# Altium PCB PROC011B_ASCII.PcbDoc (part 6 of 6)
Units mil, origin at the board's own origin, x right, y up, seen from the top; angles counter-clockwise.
Board outline 3304 x 2569 mil, 6 copper layers (TOP, L2-GND1, L3-GND/SIG, L4-GND/SIG, L5-GND2, BOTTOM), stack 55.77 mil thick; 376 components, 289 nets, 1284 pads, 1755 vias.
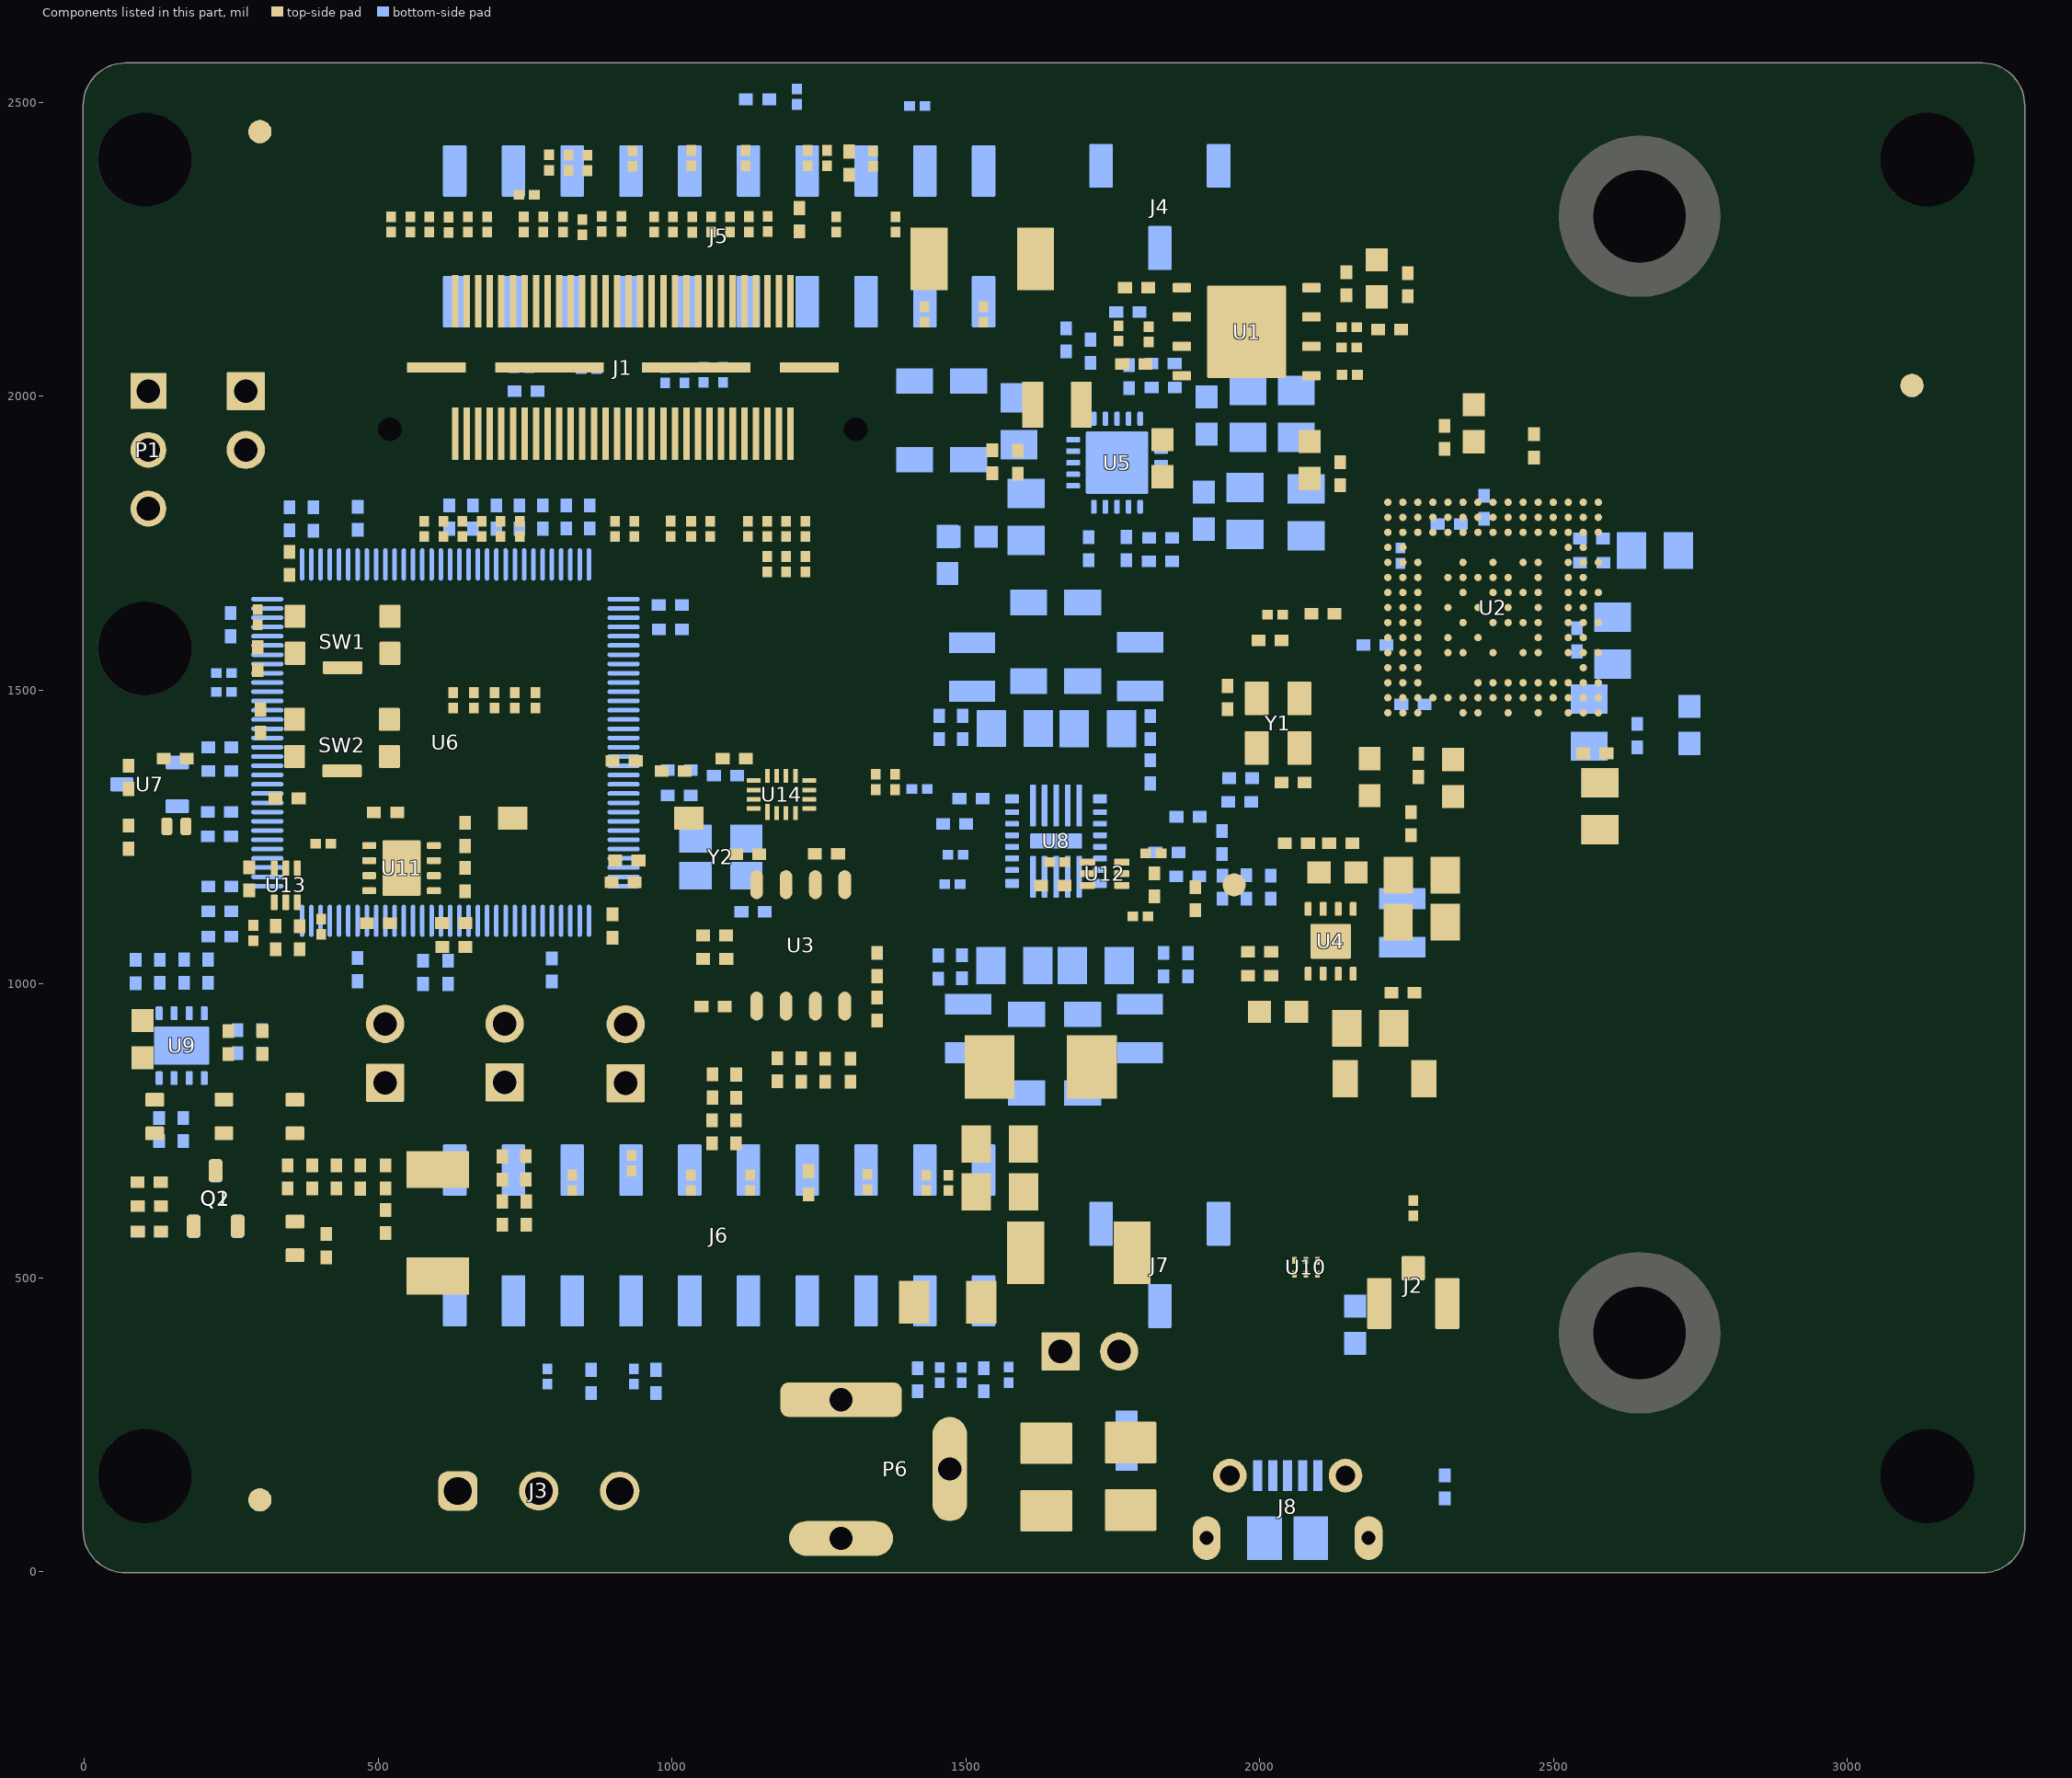
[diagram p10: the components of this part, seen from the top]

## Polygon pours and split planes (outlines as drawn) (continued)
5V_IN on TOP "TOP-5V_IN 2" (solid, pour order 995): 98 vertices, not listed, extent 511.75,336 769.75,518.6
5V_IN on TOP "TOP-5V_IN 3" (solid, remove dead copper, pour order 996): 169 vertices, not listed, extent 1558.65,336.3 1705.75,763.3
NetC1_2 on TOP "TOP-UNNAMED_41_CAPNONPOLARIZED_I63_" (solid, pour order 998): 2112.88,2196.48 2060.78,2196.48 2060.78,2172.88 2112.88,2172.88 2112.88,2196.48
5V_UNREG on TOP "TOP-5V_UNREG" (solid, pour order 1000): 122 vertices, not listed, extent 1729.45,342.3 1860.45,608.8
GND on TOP "TOP-GND" (solid, pour order 1006): 1894.98,2046.48 1842.88,2046.48 1842.88,2022.88 1894.98,2022.88 1894.98,2046.48
GND on TOP "TOP-GND 6" (solid, pour order 1014): 234 vertices, not listed, extent 1721.35,1161.1 1753.05,1226.6
GND on TOP "TOP-GND 7" (solid, pour order 1015): 162 vertices, not listed, extent 306.05,1160.99 369.63,1183.3
GND on TOP "TOP-GND 8" (solid, pour order 1016): 114 vertices, not listed, extent 1639.05,670 1773.15,928.2
GND on TOP "TOP-GND 9" (solid, pour order 1030): 217 vertices, not listed, extent 2250.67,1162.5 2332.75,1262.5
GND on TOP "TOP-GND 10" (solid, pour order 1031): 247 vertices, not listed, extent 187.75,1417.5 477.4,1552.5
GND on TOP "TOP-GND 11" (solid, pour order 1032): 146 vertices, not listed, extent 507.65,1089 572.15,1306
GND on TOP "TOP-GND 12" (solid, pour order 1036): 170 vertices, not listed, extent 1193.75,39 1828.75,265
GND on TOP "TOP-GND 14" (solid, pour order 1038): 72 vertices, not listed, extent 2573.71,1808.32 2613.84,1842.2
+3.3VD on TOP "TOP-+3.3VD" (solid, pour order 1041): 173 vertices, not listed, extent 2302.45,1845.65 2382.74,1941.4
GND on TOP "TOP-GND 3" (solid, remove dead copper, pour order 974): 2501.25,2155.5 2800.25,2155.5 2800.25,2457.5 2501.25,2457.5 2501.25,2155.5
GND on TOP "TOP-GND 13" (solid, remove dead copper, pour order 1044): 2847 vertices, not listed, extent 2201.45,15.1 3284.75,2549.4
GND on L4-GND/SIG "Top Layer-No Net" (solid, pour order 116): 43 vertices, not listed, extent 1376.03,1265.26 1898.12,2227.86
5V_UNREG on L4-GND/SIG "POWER2-No Net" (solid, remove dead copper, pour order 1046): 44 vertices, not listed, extent 1441.77,315 1865.48,1542.5
NetC85_2 on L4-GND/SIG "L4-UNNAMED_7_CAPNONPOLARIZED_I5_2" (solid, pour order 955): 96 vertices, not listed, extent 371.65,1146.2 422.25,1236.1
PMIC_1V2 on L4-GND/SIG "L4-PMIC_1V2" (solid, pour order 984): 1509 vertices, not listed, extent 1750.75,1574 2517.75,2258.4
AR_1V8 on L4-GND/SIG "L4-AR_1V8" (solid, pour order 986): 679 vertices, not listed, extent 2127.75,1077.15 2619.75,1752
5V_IN on L4-GND/SIG "L4-5V_IN" (solid, remove dead copper, pour order 997): 1026 vertices, not listed, extent 437.25,327 1727.75,2363.5
GND on L4-GND/SIG "L4-GND" (solid, pour order 1019): 555 vertices, not listed, extent 486.77,2124.33 1041.63,2468.58
GND on L4-GND/SIG "L4-GND 1" (solid, pour order 1020): 840 vertices, not listed, extent 2279.76,1480.82 2511.89,1757.58
GND on L4-GND/SIG "L4-GND 3" (solid, remove dead copper, pour order 1022): 2496 vertices, not listed, extent 16,16 3284,2549
GND on L4-GND/SIG "L4-GND 4" (solid, pour order 1023): 1170 vertices, not listed, extent 1011,2201.12 1728.04,2476.59
PMIC_2V3 on BOTTOM "BOTTOM-PMIC_2V3" (solid, pour order 958): 127 vertices, not listed, extent 1662.75,791 1947.35,900.66
PMIC_2V3 on BOTTOM "BOTTOM-PMIC_2V3 1" (solid, pour order 960): 146 vertices, not listed, extent 2140.55,968.7 2284.45,1079.3
MCU_5V on BOTTOM "BOTTOM-MCU_5V" (solid, pour order 961): 149 vertices, not listed, extent 517.75,626.5 686.75,759.5
MCU_5V on BOTTOM "BOTTOM-MCU_5V 1" (solid, pour order 964): 98 vertices, not listed, extent 1868.75,510 1993.75,651
PMIC_1V8 on BOTTOM "BOTTOM-PMIC_1V8" (solid, remove dead copper, pour order 973): 1183 vertices, not listed, extent 1339.97,801.5 1702.75,1952.5
AR_VOUT_PA on BOTTOM "BOTTOM-AR_VOUT_PA" (solid, pour order 976): 138 vertices, not listed, extent 2539.75,1315 2755.75,1427
PMIC_1V2 on BOTTOM "BOTTOM-PMIC_1V2" (solid, pour order 983): 299 vertices, not listed, extent 1663,1563 1950.75,1709.25
AR_1V8 on BOTTOM "BOTTOM-AR_1V8" (solid, pour order 987): 91 vertices, not listed, extent 2526.75,1593 2629.75,1638.98
AR_1V8 on BOTTOM "BOTTOM-AR_1V8 1" (solid, pour order 988): 124 vertices, not listed, extent 2147.75,1120 2286.65,1256.3
AR_1P3_RF2 on BOTTOM "BOTTOM-AR_1P3_RF2" (solid, pour order 990): 1059 vertices, not listed, extent 1818.8,1431.4 2987.75,2118
AR_1P3_RF1 on BOTTOM "BOTTOM-AR_1P3_RF1" (solid, pour order 992): 937 vertices, not listed, extent 1821.75,1607 2812.73,1963.7
PMICOUT_3V3 on BOTTOM "BOTTOM-PMICOUT_3V3" (solid, pour order 999): 176 vertices, not listed, extent 1453.77,1563.04 1642.75,1711.5
5V_UNREG on BOTTOM "BOTTOM-5V_UNREG" (solid, remove dead copper, pour order 1002): 183 vertices, not listed, extent 1514.45,1002.3 1620.75,1218.3
5V_UNREG on BOTTOM "BOTTOM-5V_UNREG 1" (solid, pour order 1003): 202 vertices, not listed, extent 1686.8,1002.3 1813.8,1218.5
5V_UNREG on BOTTOM "BOTTOM-5V_UNREG 2" (solid, pour order 1004): 209 vertices, not listed, extent 1687.75,1267.5 1787.85,1475.66
5V_UNREG on BOTTOM "BOTTOM-5V_UNREG 3" (solid, pour order 1005): 200 vertices, not listed, extent 1525.15,1267.5 1619.3,1475.26
GND on BOTTOM "BOTTOM-GND" (solid, pour order 1008): 21 vertices, not listed, extent 2421.7,31.02 3277.75,827.5
GND on BOTTOM "BOTTOM-GND 1" (solid, pour order 1013): 2497.25,2153.5 2796.25,2153.5 2796.25,2455.5 2497.25,2455.5 2497.25,2153.5
GND on BOTTOM "BOTTOM-GND 2" (solid, pour order 1033): 124 vertices, not listed, extent 1364.75,1971.5 1621.05,2069.85
GND on BOTTOM "BOTTOM-GND 3" (solid, pour order 1034): 510 vertices, not listed, extent 1703,307 2093.73,726.5
GND on BOTTOM "BOTTOM-GND 5" (solid, pour order 1037): 98 vertices, not listed, extent 1882.75,1982.35 2102.75,2147.5
GND on BOTTOM "BOTTOM-GND 6" (solid, pour order 1039): 239 vertices, not listed, extent 1567.7,919.3 1734.3,1218.3
GND on BOTTOM "BOTTOM-GND 7" (solid, pour order 1040): 307 vertices, not listed, extent 1568.8,1267.5 1736.9,1546
GND on BOTTOM "BOTTOM-GND 4" (solid, remove dead copper, pour order 1035): 2173 vertices, not listed, extent 1878.77,15.7 3284.85,2549.9
MCU_5V on L3-GND/SIG "L3-MCU_5V" (solid, pour order 963): 517 vertices, not listed, extent 507.75,406 1962.23,755.48
GND on L3-GND/SIG "L3-GND" (solid, pour order 1011): 2507.75,2437.5 2777.75,2437.5 2777.75,2182.5 2597.75,2182.5 2507.75,2272.5 2507.75,2437.5
GND on L3-GND/SIG "L3-GND 1" (solid, pour order 1012): 2487.75,562.5 2787.75,562.5 2787.75,262.5 2487.75,262.5 2487.75,562.5
GND on L3-GND/SIG "L3-GND 2" (solid, pour order 1024): 146 vertices, not listed, extent 1858.06,1991.53 2249.71,2152.58
GND on L3-GND/SIG "L3-GND 3" (solid, pour order 1025): 344 vertices, not listed, extent 1505.88,1776.02 1989.21,2041.98
GND on L3-GND/SIG "L3-GND 4" (solid, pour order 1026): 147 vertices, not listed, extent 231.09,1463.5 468.73,1691.74
GND on L3-GND/SIG "L3-GND 5" (solid, pour order 1027): 744 vertices, not listed, extent 991.89,593.02 1910.98,1006.2
GND on L3-GND/SIG "L3-GND 6" (solid, pour order 1028): 2622 vertices, not listed, extent 1431.33,501.13 2744.73,1845.59
GND on L3-GND/SIG "L3-GND 7" (solid, remove dead copper, pour order 1029): 3094 vertices, not listed, extent 16,16 3284,2549
GND on L2-GND1 "L5-GND" (solid, remove dead copper, pour order 1018): 553 vertices, not listed, extent 16,16 3284,2549
GND on L2-GND1 "L2-GND" (solid, pour order 1009): 2524.75,2427 2524.75,2180 2769.75,2180 2769.75,2427 2524.75,2427
GND on L2-GND1 "L2-GND 1" (solid, pour order 1010): 2527.25,529.5 2527.25,282.5 2772.25,282.5 2772.25,529.5 2527.25,529.5
GND on L5-GND2 "L5-GND" (solid, remove dead copper, pour order 1017): 553 vertices, not listed, extent 16,16 3284,2549
no net on Mechanical 6 Ass bot (solid): 340.75,2450 ccw(c298.75,2450) 298.75,2492 ccw(c298.75,2450) 256.75,2450 ccw(c298.75,2450) 298.75,2408 ccw(c298.75,2450) 340.75,2450
no net on Mechanical 6 Ass bot (solid): 340.75,122 ccw(c298.75,122) 298.75,164 ccw(c298.75,122) 256.75,122 ccw(c298.75,122) 298.75,80 ccw(c298.75,122) 340.75,122
no net on Mechanical 6 Ass bot (solid): 3150.95,2033.2 ccw(c3108.95,2033.2) 3108.95,2075.2 ccw(c3108.95,2033.2) 3066.95,2033.2 ccw(c3108.95,2033.2) 3108.95,1991.2 ccw(c3108.95,2033.2) 3150.95,2033.2
no net on Mechanical 5 Ass top (solid): 340.75,122 ccw(c298.75,122) 298.75,164 ccw(c298.75,122) 256.75,122 ccw(c298.75,122) 298.75,80 ccw(c298.75,122) 340.75,122
no net on Mechanical 5 Ass top (solid): 3152.65,2018.46 ccw(c3110.65,2018.46) 3110.65,2060.46 ccw(c3110.65,2018.46) 3068.65,2018.46 ccw(c3110.65,2018.46) 3110.65,1976.46 ccw(c3110.65,2018.46) 3152.65,2018.46
no net on Mechanical 5 Ass top (solid): 340.75,2450 ccw(c298.75,2450) 298.75,2492 ccw(c298.75,2450) 256.75,2450 ccw(c298.75,2450) 298.75,2408 ccw(c298.75,2450) 340.75,2450

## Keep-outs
TOP:
  circle w10: c3136.31,162.5 r92.09
  circle w10: c3136.31,2402.5 r92.09
  circle w10: c102.75,162.5 r92.09
  circle w10: c102.75,1570.6 r92.09
  circle w10: c102.75,2402.5 r92.09
L2-GND1:
  circle w10: c520.13,1943.64 r44.95
  circle w10: c1312.65,1943.64 r44.95
  circle w10: c3136.31,2402.5 r100.82
  circle w10: c3136.31,162.5 r100.82
  circle w10: c3136.31,2402.5 r100.82
L3-GND/SIG:
  circle w10: c3136.31,2402.5 r100.82
  circle w10: c3136.31,162.5 r100.82
L4-GND/SIG:
  circle w10: c3136.31,2402.5 r100.82
  circle w10: c3136.31,162.5 r100.82
  circle w10: c1312.65,1943.64 r44.95
L5-GND2:
  circle w10: c3136.31,162.5 r100.82
  circle w10: c3136.31,2402.5 r100.82
  circle w10: c520.13,1943.64 r44.95
  circle w10: c1312.65,1943.64 r44.95
BOTTOM:
  circle w1: c3110.08,2018.14 r44
  circle w10: c3136.31,2402.5 r92.09
  circle w10: c3136.31,162.5 r92.09
Keep-Out Layer:
  text "KEEP OUT LAYER" at -1318.01,-1032.33 h75

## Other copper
TOP:
  text "TOP" at -1316.15,-1038.69 h75
L2-GND1:
  text "LAYER-2 GND1" at -1293.22,-1034.39 h75
L3-GND/SIG:
  text "LAYER-3 GND/SIGNAL" at -1349.73,-1034.31 h75
L4-GND/SIG:
  text "LAYER-4 GND/SIGNAL" at -1322.23,-1041.27 h75
L5-GND2:
  text "LAYER-5 GND2" at -1308.33,-1043.01 h75
BOTTOM:
  text "BOTTOM" at -1318.46,-1042.03 h75

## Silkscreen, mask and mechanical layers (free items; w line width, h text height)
Top Overlay:
  lines w10: 176.28,1919.69 179.6,1919.69 193.53,1905.76 193.53,1794.32 187.71,1800.14 200.17,1800.14 194.35,1794.32
  lines w30: 1378.75,904.5 1378.75,818 1459.85,818 ; 1378.75,1094.5 1378.75,1274.5 ; 1382.75,1830 1382.75,2242 ; 1700.75,2258 2146.75,2258 ; 1786.25,818 2088.75,818 ; 2268.75,2258 2474.75,2258 ; 2770.75,1968 2770.75,2182
  text "HD_CONN" at 467.92,2015.1 h30 r90
  text "VPP_1P7" at 381.32,1862.65 h30 r90
  text "1642-EVM" at 813.79,1694.33 h30
  text "GND" at 209.45,1680.5 h30 r90
  text "PROC011" at 775,1637.52 h30
  text "REV B" at 969.45,1635.95 h30
  text "GPIO1" at 620.25,1543 h30 r90
  text "ON" at 1079.14,1311 h30 r90
  text "NRST" at 615.01,1295.07 h30 r90
  text "SPI" at 709,1164 h30 r90
  text "CAN" at 1079.14,1153 h30 r90
  text "SOP0" at 1025.49,883.72 h30 r90
  text "5V" at 385.25,854.5 h30 r90
  text "NERR_OUT" at 211.42,848.5 h30 r90
  text "SOP1" at 821.68,840.86 h30 r90
  text "SOP2" at 615.55,835.13 h30 r90
  text "NRST" at 404.16,399.06 h30 r90
  text "5V_IN" at 1194.75,354 h30 r90
  text "GND" at 790.25,294 h30 r90
  text "CAN_L" at 1066.42,227.5 h30 r90
  text "CAN_H" at 542.42,226.5 h30 r90
  text "USB" at 2011.93,198.27 h30
  text "SILKSCREEN TOP" at -1339.97,-1029.03 h60
Bottom Overlay:
  drawing of 8192 lines, arcs and shapes, not listed
  text "GND" at 1745.25,2556 h30 r90
  text "GND" at 1845.25,2556 h30 r90
  text "3V3" at 1943.47,2549.66 h30 r90
  text "GND" at 596.45,2529.6 h30 r90
  text "20" at 1634.19,2423.68 h30 r90
  text "2" at 552.36,2404.47 h30 r90
  text "19" at 1638.64,2210.67 h30 r90
  text "1" at 544.91,2180.78 h30 r90
  text "P1" at 132.79,2073.5 h30
  text "P7" at 396.41,2020 h30
  text "P4" at 955.85,1005.8 h30
  text "P3" at 537.9,1001.27 h30
  text "P2" at 736.23,1000.15 h30
  text "GND" at 790.25,886 h30 r90
  text "GND" at 1845.25,776 h30 r90
  text "GND" at 1735.25,771 h30 r90
  text "20" at 1641.82,729.19 h30 r90
  text "2" at 553.44,705.94 h30 r90
  text "19" at 1656.65,524.84 h30 r90
  text "1" at 545.99,482.25 h30 r90
  text "P6" at 1317.41,338.79 h30
  text "P5" at 1877.7,327.72 h30
  text "J3" at 538.18,135.69 h30
  text "SILKSCREEN BOTTOM" at -1330.97,-1032.41 h75
Top Paste:
  text "SOLDERPASTE TOP" at -1322.76,-1029.77 h75
Bottom Paste:
  text "SOLDERPASTE BOTTOM" at -1315.43,-1031.21 h75
Top Solder:
  text "SOLDERMASK TOP" at -1325.23,-1033.37 h75
Bottom Solder:
  text "SOLDERMASK BOTTOM" at -1292.25,-1013.98 h75
OUTLINE:
  lines w4: 0,70 ccw(c70,70) 70,0 3230,0 ccw(c3230,70) 3300,70 3300,2495 ccw(c3230,2495) 3230,2565 70,2565 ccw(c70,2495) 0,2495 0,70
Board Dimensions:
  text "AT 4 PLACES" at -810,-280 h75
Mechanical 5 Ass top:
  lines w6: 163,2270 163,2286 174,2297 355,2297 405,2247 741,2247 747,2253 747,2256 ; 355.14,2202 420,2202 435,2217 897.05,2217 912,2231.95 912,2254 ; 974,2330 974,2349.96 985.04,2361 1276.02,2361 1291.02,2346 1361,2346 1376,2361 1376,2381 1391,2396 ; 1162.65,2337 1162.65,2337.65 1171,2346 1256.78,2346 1269.78,2333 1574,2333 1604,2363 1604,2371 ; 2111,2139 2111,2127.39 2113.39,2125
  lines w10: -2151.07,-1099.34 4448.93,-1099.34 ; -2151.07,-896 4450.93,-896 ; -2151.07,-692.67 -2151.07,-1302.67 1853.93,-1302.67 4450.93,-1302.67 4450.93,-692.67 -2150.57,-692.67 -2150.57,-1302.67 -575.07,-1302.67 ; 313.93,-1302.67 313.93,-692.67 ; 1580.93,-896 1580.93,-692.67 ; 2420.93,-896 2420.93,-692.67 ; 3042.93,-1309.17 3042.93,-1106.34
  text "COMPONENTS MARKED 'DNP' SHOULD NOT BE POPULATED." at -1592.26,2897.89 h60
  text "ASSEMBLY VARIANT:" at -1592.76,2782.39 h60
  text ".VariantName" at -556.76,2782.39 h60
  text "PCB VIEWED FROM TOP SIDE" at -2087.57,-824.84 h60
  text "BOARD #:" at 388.93,-824.84 h60
  text ".PRJ_Number" at 934.43,-824.84 h60
  text "REV:" at 1778.93,-824.84 h60
  text ".PCB_Rev" at 2070.43,-824.84 h60
  text "SVN REV:" at 2616.93,-824.84 h60
  text ".VersionControl_RevNumber" at 3122.93,-824.84 h60
  text "Assembly TOP" at -1818.81,-1016.17 h60
  text "TID #:" at 388.93,-1028.17 h60
  text ".TID" at 934.43,-1028.17 h60
  text "PLOT NAME =" at -2087.57,-1233.51 h60
  text ".plot_File_Name" at -1282.07,-1233.51 h35
  text "GENERATED    :" at 390.93,-1233.51 h60
  text ".Print_Date" at 1260.43,-1233.51 h60
  text ".Print_Time" at 1989.43,-1233.51 h60
  text "TEXAS INSTRUMENTS" at 3253.93,-1233.51 h60
Mechanical 6 Ass bot:
  lines w10: -2151.07,-896 4450.93,-896 ; -2149.07,-1099.34 4450.93,-1099.34 ; -743.07,-1309.17 -743.07,-1106.34 ; -121.07,-896 -121.07,-692.67 ; 718.93,-896 718.93,-692.67 ; 1985.93,-1302.67 1985.93,-692.67 ; 2874.93,-1302.67 4450.43,-1302.67 4450.43,-692.67 -2151.07,-692.67 -2151.07,-1302.67 445.93,-1302.67 4450.93,-1302.67 4450.93,-692.67
  text "COMPONENTS MARKED 'DNP' SHOULD NOT BE POPULATED." at 4243.43,-486.67 h60
  text ".VariantName" at 3199.43,-602.67 h60
  text "ASSEMBLY VARIANT:" at 4238.43,-602.67 h60
  text ".VersionControl_RevNumber" at -823.07,-824.84 h60
  text "SVN REV:" at -317.07,-824.84 h60
  text ".PCB_Rev" at 229.43,-824.84 h60
  text "REV:" at 520.93,-824.84 h60
  text ".PRJ_Number" at 1365.43,-824.84 h60
  text "BOARD #:" at 1910.93,-824.84 h60
  text "PCB VIEWED FROM BOTTOM SIDE" at 4387.43,-824.84 h60
  text ".TID" at 1365.43,-1028.17 h60
  text "TID #:" at 1910.93,-1028.17 h60
  text "ASSEMBLY BOTTOM" at 4003,-1028 h60
  text "TEXAS INSTRUMENTS" at -954.07,-1233.51 h60
  text ".Print_Time" at 310.43,-1233.51 h60
  text ".Print_Date" at 1039.43,-1233.51 h60
  text "GENERATED    :" at 1908.93,-1233.51 h60
  text ".plot_File_Name" at 3581.93,-1233.51 h35
  text "PLOT NAME =" at 4387.43,-1233.51 h60
M9 Title Sheet:
  lines w10: -2351.2,871.62 -2151.2,871.62 ; -2351.2,3246.62 -2151.2,3246.62 ; -2351.2,5621.62 -2151.2,5621.62 ; 148.8,-1503.38 148.8,-1303.38 ; 148.8,7796.62 148.8,7996.62 ; 2648.8,-1503.38 2648.8,-1303.38 ; 2648.8,7796.62 2648.8,7996.62 ; 4461.3,-1303.38 4461.3,-693.38 9443.8,-693.38 ; 5148.8,-1503.38 5148.8,-1303.38 ; 5148.8,7796.62 5148.8,7996.62 ; 7648.8,-1503.38 7648.8,-1303.38 ; 7648.8,7796.62 7648.8,7996.62 ; 9443.8,-1303.38 9443.8,-693.38 ; 9443.8,-993.38 12443.8,-993.38 ; 9443.8,-393.38 12443.8,-393.38 ; 9444.8,200.62 12444.8,200.62 ; 10148.8,-1503.38 10148.8,-1303.38 ; 10148.8,7796.62 10148.8,7996.62 ; 10948.8,-1293.38 10948.8,-693.38 ; 12443.8,-693.38 9443.8,-693.38 ; 12443.8,-93.38 9443.8,-93.38 ; 12448.8,-103.38 12448.8,-1303.38 ; 12448.8,701.12 9444.8,701.12 9443.8,701.12 9443.8,200.62 9443.8,-93.38 ; 12448.8,871.62 12648.8,871.62 ; 12448.8,3246.62 12648.8,3246.62 ; 12448.8,5621.62 12648.8,5621.62 ; 9443.8,-693.38 9443.8,-93.38 ; 12448.8,-1303.38 -2151.2,-1303.38 -2151.2,7796.62 12448.8,7796.62 12448.8,-1303.38 ; -2351.2,-1503.38 12648.8,-1503.38 12648.8,7996.62 -2351.2,7996.62 -2351.2,-1503.38
  text "1" at -1119.86,7866.62 h70
  text "2" at 1375.8,7866.62 h70
  text "3" at 3865.14,7866.62 h70
  text "4" at 6371.81,7866.62 h70
  text "5" at 8870.8,7866.62 h70
  text "6" at 11375.8,7866.62 h70
  text "A" at -2276.2,6723.62 h70
  text "A" at 12523.8,6723.62 h70
  text "B" at -2276.2,4343.62 h70
  text "B" at 12523.8,4343.62 h70
  text "C" at -2276.2,1968.62 h70
  text "C" at 12523.8,1968.62 h70
  text "PROJECT TITLE:" at 9483.8,107.62 h45
  text ".PRJ_Title" at 9533.8,-25.71 h50
  text "DESIGNED FOR:" at 9483.8,-193.38 h45
  text ".PRJ_Customer" at 9533.8,-333.38 h70
  text "D" at -2276.2,-401.38 h70
  text "D" at 12523.8,-401.38 h70
  text "FILE NAME:" at 9483.8,-493.38 h45
  text ".PCB_File_Name_No_Path" at 9533.8,-613.38 h70
  text "Texas Instruments (TI) and/or its licensors do not warrant the accuracy or completeness of this specification" at 4514.3,-775.22 h45
  text "ENGINEER:" at 9483.8,-783.38 h45
  text "LAYOUT BY:" at 10988.8,-783.38 h45
  text "or any information contained therein. TI and/or its licensors do not warrant that this design will meet" at 4469.31,-887.88 h45
  text ".PRJ_Engineer" at 9533.8,-938.37 h70
  text ".PCB_Layout" at 11039.3,-938.37 h70
  text "the specifications, will be suitable for your application or fit for any particular purpose, or will operate in" at 4469.31,-1000.55 h45
  text "ALTIUM DESIGNER VERSION:" at 10988.8,-1093.38 h45
  text "an implementation. TI and/or its licensors do not warrant that the design is production worthy. You should" at 4469.31,-1113.21 h45
  text "completely validate and test your design implementation to confirm the system functionality for your application." at 4514.3,-1225.88 h45
  text ".print_Scale" at 9533.8,-1226.71 h70
  text ".Application_BuildNumber" at 11039.3,-1226.71 h70
  text "1" at -1119.86,-1433.38 h70
  text "2" at 1375.8,-1433.38 h70
  text "3" at 3865.14,-1433.38 h70
  text "4" at 6371.81,-1433.38 h70
  text "5" at 8870.8,-1433.38 h70
  text "6" at 11375.8,-1433.38 h70
LOGO_HOT:
  drawing of 189 lines, arcs and shapes, not listed
  text "DESIGN INFORMATION" at 10521.82,6186.29 h60
  text "MIL" at 11183,6056 h60
  text "MIN. TRACK WIDTH:" at 9877.26,6054.17 h60
  text "4" at 10973.5,6054.17 h60
  text "4" at 10965.36,5957.06 h60
  text "MIL" at 11182.26,5931 h60
  text "MIN. CLEARANCE:" at 9877.26,5930.04 h60
  text "MIL" at 11185,5807 h60
  text "MIN. VIA PAD SIZE:" at 9877.26,5805.92 h60
  text "13.77" at 10873,5798 h60
  text "0.05mm (2MIL)" at 10572.26,5676.02 h60
  text "MINIMUM ANNULAR RING" at 9548.03,5667.79 h60
  text "EXTERNAL" at 11280.26,5667.79 h60
  text "PER" at 9748.03,5557.67 h60
  text "IPC-D-275 CLASS 2 LEVEL C" at 9968.03,5557.66 h60
  text "MIL, HOLES" at 11456.26,5457.19 h60
  text "+/-" at 11063.8,5448.6 h60
  text "+/-" at 11917.8,5448.6 h60
  text "REGISTRATION TOLERANCES:" at 9548.03,5447.54 h60
  text "METAL" at 10747.8,5447.54 h60
  text "2" at 11324,5447.54 h60
  text "3" at 12157,5447.54 h60
  text "MIL" at 12273.26,5447.54 h60
  text "HOLE SIZE TOLERANCE (UNLESS OTHERWISE SPECIFIED):" at 9548.03,5349.22 h60
  text "+/-" at 11917.8,5346.35 h60
  text "3" at 12157,5345.29 h60
  text "MIL" at 12273.26,5345.29 h60
  text "MATERIAL:" at 9473.26,5207.64 h60
  text "FR-4 High Tg" at 10459.7,5079.12 h60
  text "X" at 11197.39,5075.36 h60
  text "FR-408" at 9894.26,5066.61 h60
  text "OTHER" at 11382.26,5066.61 h60
  text "REFER STACKUP" at 11710.91,5051.35 h60
  text "THICKNESS:" at 9489.68,4927.16 h60
  text "X" at 10000.66,4924.28 h60
  text "56.21 MIL (1.43mm) +/-10%" at 10100.96,4922.18 h60
  text "OTHER" at 11499.26,4915.36 h60
  text "TOLERANCE:" at 9548.03,4777.04 h60
  text "X" at 10396.26,4777.04 h60
  text "ANSI IPC-6012 TYPE 3 CLASS 2" at 10574.28,4777.04 h60
  text "OTHER +/-" at 10574.26,4632.85 h60
  text "BOW & TWIST:" at 9548.03,4487.66 h60
  text "X" at 10396.26,4487.66 h60
  text "ANSI IPC-6012 TYPE 3 CLASS 2" at 10574.28,4487.66 h60
  text "OTHER +/-" at 10574.26,4340.97 h60
  text "DRILLING:" at 9473.26,4210.35 h60
  text "NC_DRILL FILES" at 11234.26,4105.16 h60
  text "REFERENCE:" at 9548.03,4101.22 h60
  text "X" at 10205.26,4101.13 h60
  text "AS SHOWN" at 10383.26,4101.22 h60
  text "X" at 11106.26,4101.22 h60
  text "OTHER" at 11532.26,3958.97 h60
  text "PTH COPPER THICKNESS:" at 9547.71,3955.44 h60
  text "X" at 10686.94,3955.44 h60
  text "20-30 um" at 10814.94,3955.44 h60
  text "BOARD FINISH:" at 9473.26,3807.85 h60
  text "SILKSCREEN:" at 9628.48,3697.72 h60
  text "X" at 10586.26,3697.72 h60
  text "TOP" at 10703.26,3697.72 h60
  text "X" at 11096.26,3697.72 h60
  text "BOTTOM" at 11214.26,3697.72 h60
  text "SILKSCREEN COLOR:" at 9628.48,3542.53 h60
  text "X" at 10585.26,3542.53 h60
  text "WHITE" at 10703.26,3542.53 h60
  text "OTHER" at 11214.26,3542.53 h60
  text "GREEN" at 10834.26,3399.08 h60
  text "OTHER" at 11452.26,3399.08 h60
  text "X" at 11296.74,3395.1 h60
  text "RED" at 11875.95,3395.11 h60
  text "SOLDER RESIST COLOR:" at 9628.48,3392.22 h60
  text "X" at 10716.26,3244.83 h60
  text "MATTE" at 10834.26,3244.83 h60
  text "SEMI-GLOSS" at 11451.8,3244.19 h60
  text "IMMERSION GOLD (ENIG)" at 10534.26,3072.06 h60
  text "ENEPIG" at 11871.8,3064.84 h60
  text "SURFACE FINISH:" at 9473.26,3063.84 h60
  text "IMM SILVER" at 11653,2932 h60
  text "IMM. TIN/SILVER OR EQUIV" at 9802.8,2926.52 h60
  text "X" at 11058.66,2926.28 h60
  text "OTHER" at 11234.26,2922.59 h60
  text "ARRAY/PANEL:" at 9473.26,2767.21 h60
  text "CUT AND TRIM PER M1 BOARD OUTLINE" at 10534.26,2758.99 h60
  text "X" at 10355.66,2746.28 h60
  text "N.C. ROUTE" at 10534.26,2623.02 h60
  text "V. SCORE" at 11400.26,2623.02 h60
  text "CERTIFICATION:" at 9473.26,2493.89 h60
  text "MATERIALS AND WORKMANSHIP FOR ALL PCBS" at 10198.26,2493.89 h60
  text "TO MEET OR EXCEED THE REQUIREMENTS OF:" at 10198.26,2399.83 h60
  text "X" at 9835.77,2271.2 h60
  text "ANSI IPC-A-600F CLASS ->" at 9963.76,2271.2 h60
  text "X" at 11611.77,2271.2 h60
  text "2" at 11721.76,2271.2 h60
  text "1" at 11406.76,2269.7 h60
  text "3" at 12075.76,2269.7 h60
  text "X" at 10647.77,2123.51 h60
  text "RoHS" at 10775.76,2123.51 h60
  text "OTHER" at 11420.16,2123.51 h60
  text "PER ORDER" at 11817.22,2123.51 h60
  text "ALL BOARDS MUST MEET OR EXCEED UL94-V0 REQUIREMENTS." at 9500.8,1969.69 h60
  text "PCB MUST BEAR THE UL94V-0 UL REGISTERED MATERIAL ID NUMBER" at 9500.8,1853.62 h60
  text "ADDITIONAL REQUIREMENTS:" at 9473.26,1684.2 h60
  text "MICROSECTION:" at 9548.03,1577.07 h60
  text "YES" at 10453.76,1577.07 h60
  text "REQUIRED" at 11315.26,1432.74 h60
  text "BARE BOARD ELEC. TEST:" at 9548.03,1429.88 h60
  text "NONE" at 10853.76,1429.88 h60
  text "X" at 11197.26,1429.88 h60
  text "PER ORDER" at 11907.26,1429.88 h60
  text "XX MIL VIAS REQUIRE NON-CONDUCTIVE FILL AND PLANARIZE" at 9662.75,1281.5 h59
  text "XX MIL VIAS REQUIRE CONDUCTIVE FILL AND PLANARIZE" at 9648.75,1125.5 h60
  text "OUTER XX MIL TRACES REQUIRE 50 OHM SINGLE-ENDED IMPEDANCE" at 9641.75,955.5 h58
  text "OUTER XX ML TRACES REQUIRE 100 OHM DIFFERENTIAL PAIR" at 9662.75,834.5 h60
  text "IMPEDANCE CONTROL TRACES" at 9741.75,726.5 h60
M11 Gerber Information:
  lines w10: -2151.29,-1100.49 4448.71,-1100.49 ; -2151.29,-897.15 4450.71,-897.15 ; -2151.29,-693.82 -2151.29,-1303.82 1853.71,-1303.82 4450.71,-1303.82 4450.71,-693.82 -2150.79,-693.82 -2150.79,-1303.82 -575.29,-1303.82 ; 313.71,-1303.82 313.71,-693.82 ; 1580.71,-897.15 1580.71,-693.82 ; 2420.71,-897.15 2420.71,-693.82 ; 3052.83,-1282.27 3052.83,-1079.44
  text "ALL ARTWORK VIEWED FROM TOP SIDE" at -2087.79,-825.99 h60
  text "BOARD #:" at 388.71,-825.99 h60
  text ".PRJ_Number" at 934.21,-825.99 h60
  text "REV:" at 1778.71,-825.99 h60
  text ".PCB_Rev" at 2070.21,-825.99 h60
  text "SVN REV:" at 2616.71,-825.99 h60
  text ".VersionControl_RevNumber" at 3122.71,-825.99 h60
  text "LAYER NAME =" at -2087.79,-1028.81 h60
  text "TID #:" at 388.71,-1029.32 h60
  text ".TID" at 934.21,-1029.32 h60
  text ".plot_File_Name" at -1429,-1231 h50
  text "PLOT NAME =" at -2087.79,-1234.65 h60
  text "GENERATED    :" at 390.71,-1234.65 h60
  text ".Print_Date" at 1260.21,-1234.65 h60
  text ".Print_Time" at 1989.21,-1234.65 h60
  text "TEXAS INSTRUMENTS" at 3253.71,-1234.65 h60
Mechanical 12:
  drawing of 399 lines, arcs and shapes, not listed
  text "Layer" at 3775.5,7076.5 h60
  text "Name" at 4185.41,7076.5 h60
  text "Material" at 5115.16,7076.5 h60
  text "Thickness" at 5974.92,7076.5 h60
  text "Constant" at 6624.76,7076.5 h60
  text "Board Layer Stack" at 7194.62,7076.5 h60
  text "1" at 3775.5,6956.5 h60
  text "Top Overlay" at 4185.41,6956.5 h60
  text "2" at 3775.5,6836.5 h60
  text "Top Solder" at 4185.41,6836.5 h60
  text "Solder Resist" at 5115.16,6836.5 h60
  text "0.80mil" at 5974.92,6836.5 h60
  text "0" at 6624.76,6836.5 h60
  text "3" at 3775.5,6716.5 h60
  text "TOP" at 4185.41,6716.5 h60
  text "Copper" at 5115.16,6716.5 h60
  text "1.60mil" at 5974.92,6716.5 h60
  text "4" at 3775.5,6596.5 h60
  text "Dielectric1" at 4185.41,6596.5 h60
  text "RO4835 LOPRO" at 5115.16,6596.5 h60
  text "4.00mil" at 5974.92,6596.5 h60
  text "3.66" at 6624.76,6596.5 h60
  text "5" at 3775.5,6476.5 h60
  text "L2-GND1" at 4185.41,6476.5 h60
  text "Copper" at 5115.16,6476.5 h60
  text "1.40mil" at 5974.92,6476.5 h60
  text "6" at 3775.5,6356.5 h60
  text "Dielectric2" at 4185.41,6356.5 h60
  text "370HR" at 5115.16,6356.5 h60
  text "5.67mil" at 5974.92,6356.5 h60
  text "3.9" at 6624.76,6356.5 h60
  text "7" at 3775.5,6236.5 h60
  text "L3-GND/SIG" at 4185.41,6236.5 h60
  text "Copper" at 5115.16,6236.5 h60
  text "1.20mil" at 5974.92,6236.5 h60
  text "8" at 3775.5,6116.5 h60
  text "Dielectric3" at 4185.41,6116.5 h60
  text "370HR" at 5115.16,6116.5 h60
  text "28.00mil" at 5974.92,6116.5 h60
  text "4.36" at 6624.76,6116.5 h60
  text "9" at 3775.5,5996.5 h60
  text "L4-GND/SIG" at 4185.41,5996.5 h60
  text "Copper" at 5115.16,5996.5 h60
  text "1.20mil" at 5974.92,5996.5 h60
  text "10" at 3775.5,5876.5 h60
  text "Dielectric4" at 4185.41,5876.5 h60
  text "370HR" at 5115.16,5876.5 h60
  text "5.90mil" at 5974.92,5876.5 h60
  text "3.9" at 6624.76,5876.5 h60
  text "11" at 3775.5,5756.5 h60
  text "L5-GND2" at 4185.41,5756.5 h60
  text "Copper" at 5115.16,5756.5 h60
  text "1.20mil" at 5974.92,5756.5 h60
  text "12" at 3775.5,5636.5 h60
  text "Dielectric5" at 4185.41,5636.5 h60
  text "370HR" at 5115.16,5636.5 h60
  text "4.00mil" at 5974.92,5636.5 h60
  text "4.26" at 6624.76,5636.5 h60
  text "13" at 3775.5,5516.5 h60
  text "BOTTOM" at 4185.41,5516.5 h60
  text "Copper" at 5115.16,5516.5 h60
  text "1.60mil" at 5974.92,5516.5 h60
  text "14" at 3775.5,5396.5 h60
  text "Bottom Solder" at 4185.41,5396.5 h60
  text "Solder Resist" at 5115.16,5396.5 h60
  text "0.80mil" at 5974.92,5396.5 h60
  text "0" at 6624.76,5396.5 h60
  text "15" at 3775.5,5276.5 h60
  text "Bottom Overlay" at 4185.41,5276.5 h60
Mechanical 14:
  text "NOTES: UNLESS OTHERWISE SPECIFIED." at 3982.31,2648.8 h60
  text "1. ALL VIAS ARE TENTED ON BOTH SIDES UNLESS SOLDERMASK OPENED IN GERBER." at 3986.8,2136.01 h60
  text "2. ALL VIAS ON PAD INCLUDING BGA AREA SHOULD BE FILLED WITH NON CONDUCTIVE EPOXY AND SURFACE SHOULD BE FLAT" at 3988.14,1986.34 h60
  text "BGA AREA VIAS SHOULD BE CAPPED WITH COPPER PLATING TO ENSURE FLAT SURFACE" at 4158.14,1879.34 h60
  text "REFER VIA FILL DOCUMENT TO IDENTIFY THE VIAS TO BE FILLED" at 4158.14,1775.34 h60
  text "FLATNESS TOLERANCE FOR VIA ON PADS: +0.000 /- 0.001 INCHES ON BOTH SIDES." at 4158.14,1666.34 h60
  text "3. MANUFACTURER'S IDENTIFICATION,DATECODE LETTER SHALL BE SILKSCREENED ON SOLDER SIDE" at 3974.61,1494.94 h60
  text "OF THE BOARD." at 4144.61,1381.94 h60
  text "4. TRACE WIDTH SHOULD BE ACCURATELY ETCHED. MAX TOLERANCE +/- 1 MIL" at 3974.61,1267.94 h60
  text "5. REFER STACKUP DOCUMENT FOR IMPEDANCE CONTROL TRACES ON LAYER 1." at 3960,1134.48 h60
  text "50 OHM SINGLE ENDED AND 100 OHM DIFFERENTIAL IMPEDANCE CONTROL TRACES." at 4071,1023 h60
  text "6. SOLDER MASK OPENING IS KEPT SAME SIZE AS PAD (1:1)." at 3980,876.35 h60
  text "THE MANUFACTURER IS REQUESTED TO RESIZE IT AS PER THEIR SOLDERMASK TOLERANCE EXCEPT NPTH DRILL AND FIDUCIALS." at 4090,722.46 h60
Mechanical 16:
  lines w0.16: -48930.49,-49088.31 cw(c-48930.49,-49085.55) -48933.25,-49085.55 -48933.25,-48990.08 cw(c-48930.49,-48990.08) -48930.49,-48987.32
  lines w0.79: -48810.48,-49133.52 -48810.48,-49166 -48672.68,-49166 -48672.68,-49133.52 ; -48769.14,-49166 -48769.14,-49133.52
FAB_DWG:
  circle w10: c54,5806.91 r27.55
  circle w10: c54,5435.03 r16.53
  circle w10: c54,5435.03 r27.55
  lines w10: 26.45,5531.44 81.55,5531.44 81.55,5586.54 26.45,5586.54 26.45,5531.44 ; 26.45,5669.18 40.23,5669.18 54,5655.4 67.77,5669.18 81.55,5669.18 67.77,5682.95 81.55,5696.72 67.77,5696.72 54,5710.49 40.23,5696.72 26.45,5696.72 40.23,5682.95 26.45,5669.18 ; 26.45,5958.41 81.55,5958.41 54,5903.32 26.45,5958.41 ; 26.45,6027.27 81.55,6027.27 81.55,6082.37 26.45,6082.37 26.45,6027.27 ; 26.45,6165 40.23,6165 40.23,6151.23 67.77,6151.23 67.77,6165 81.55,6165 81.55,6192.55 67.77,6192.55 67.77,6206.32 40.23,6206.32 40.23,6192.55 26.45,6192.55 26.45,6165 ; 26.45,6275.19 54,6288.96 81.55,6275.19 67.77,6302.74 81.55,6330.28 54,6316.51 26.45,6330.28 40.23,6302.74 26.45,6275.19 ; 26.45,6399.15 26.45,6412.92 40.23,6426.69 26.45,6440.47 26.45,6454.24 40.23,6454.24 54,6440.47 67.77,6454.24 81.55,6454.24 81.55,6440.47 67.77,6426.69 81.55,6412.92 81.55,6399.15 67.77,6399.15 54,6412.92 40.23,6399.15 26.45,6399.15 ; 26.45,6550.65 54,6523.1 81.55,6550.65 54,6578.2 26.45,6550.65 ; 26.45,6660.83 40.23,6660.83 54,6647.06 67.77,6660.83 81.55,6660.83 67.77,6674.61 81.55,6688.38 67.77,6688.38 54,6702.15 40.23,6688.38 26.45,6688.38 40.23,6674.61 26.45,6660.83 ; 26.45,6826.11 81.55,6826.11 54,6771.02 26.45,6826.11 ; 37.47,5542.46 70.53,5542.46 70.53,5575.52 37.47,5575.52 37.47,5542.46 ; 37.47,6666.34 45.74,6666.34 54,6658.08 62.26,6666.34 70.53,6666.34 62.26,6674.61 70.53,6682.87 62.26,6682.87 54,6691.14 45.74,6682.87 37.47,6682.87 45.74,6674.61 37.47,6666.34 ; 37.47,6815.09 70.53,6815.09 54,6782.04 37.47,6815.09 ; 3363.45,4119.27 3391,4133.05 3418.55,4119.27 3404.77,4146.82 3418.55,4174.36 3391,4160.59 3363.45,4174.36 3377.23,4146.82 3363.45,4119.27 ; 3374.47,4130.29 3391,4138.55 3407.53,4130.29 3399.26,4146.82 3407.53,4163.35 3391,4155.08 3374.47,4163.35 3382.74,4146.82 3374.47,4130.29
  lines w15: -23.5,6857.79 2459.39,6857.79 ; 295.25,5370.3 295.25,6981.75 ; 537.73,5370.3 537.73,6981.75 ; 1110.2,5370.3 1110.2,6981.75 ; 1682.68,5370.3 1682.68,6981.75 ; 1929.88,5370.3 1929.88,6981.75 ; 3313.5,4206.04 5579.9,4206.04 ; 3632.25,4082.09 3632.25,4330 ; 3874.73,4082.09 3874.73,4330 ; 4391.25,4082.09 4391.25,4330 ; 4803.19,4082.09 4803.19,4330 ; 5050.39,4082.09 5050.39,4330 ; -23.5,5370.3 2459.39,5370.3 2459.39,6981.75 -23.5,6981.75 -23.5,5370.3 ; 3313.5,4082.09 5579.9,4082.09 5579.9,4330 3313.5,4330 3313.5,4082.09
  text "Symbol" at 50.87,6894.98 h72
  text "Count" at 332.44,6894.98 h72
  text "Hole Size" at 574.91,6894.98 h72
  text "Hole Length" at 1147.39,6894.98 h72
  text "Plated" at 1719.87,6894.98 h72
  text "Drill Layer Pair" at 1967.07,6894.98 h72
  text "9" at 332.44,6771.02 h60
  text "7.87mil (0.200mm)" at 574.91,6771.02 h60
  text "-" at 1147.39,6771.02 h60
  text "PTH" at 1719.87,6771.02 h60
  text "TOP - BOTTOM" at 1967.07,6771.02 h60
  text "1046" at 332.44,6647.06 h60
  text "12.20mil (0.310mm)" at 574.91,6647.06 h60
  text "-" at 1147.39,6647.06 h60
  text "PTH" at 1719.87,6647.06 h60
  text "TOP - BOTTOM" at 1967.07,6647.06 h60
  text "2" at 332.44,6523.1 h60
  text "23.62mil (0.600mm)" at 574.91,6523.1 h60
  text "51.18mil (1.300mm)" at 1147.39,6523.1 h60
  text "PTH" at 1719.87,6523.1 h60
  text "TOP - BOTTOM" at 1967.07,6523.1 h60
  text "2" at 332.44,6399.15 h60
  text "33.47mil (0.850mm)" at 574.91,6399.15 h60
  text "-" at 1147.39,6399.15 h60
  text "PTH" at 1719.87,6399.15 h60
  text "TOP - BOTTOM" at 1967.07,6399.15 h60
  text "2" at 332.44,6275.19 h60
  text "39.37mil (1.000mm)" at 574.91,6275.19 h60
  text "118.11mil (3.000mm)" at 1147.39,6275.19 h60
  text "PTH" at 1719.87,6275.19 h60
  text "TOP - BOTTOM" at 1967.07,6275.19 h60
  text "1" at 332.44,6151.23 h60
  text "39.37mil (1.000mm)" at 574.91,6151.23 h60
  text "137.79mil (3.500mm)" at 1147.39,6151.23 h60
  text "PTH" at 1719.87,6151.23 h60
  text "TOP - BOTTOM" at 1967.07,6151.23 h60
  text "10" at 332.44,6027.27 h60
  text "40.00mil (1.016mm)" at 574.91,6027.27 h60
  text "-" at 1147.39,6027.27 h60
  text "PTH" at 1719.87,6027.27 h60
  text "TOP - BOTTOM" at 1967.07,6027.27 h60
  text "2" at 332.44,5903.32 h60
  text "40.16mil (1.020mm)" at 574.91,5903.32 h60
  text "-" at 1147.39,5903.32 h60
  text "NPTH" at 1719.87,5903.32 h60
  text "TOP - BOTTOM" at 1967.07,5903.32 h60
  text "3" at 332.44,5779.36 h60
  text "40.16mil (1.020mm)" at 574.91,5779.36 h60
  text "-" at 1147.39,5779.36 h60
  text "PTH" at 1719.87,5779.36 h60
  text "TOP - BOTTOM" at 1967.07,5779.36 h60
  text "3" at 332.44,5655.4 h60
  text "47.24mil (1.200mm)" at 574.91,5655.4 h60
  text "-" at 1147.39,5655.4 h60
  text "PTH" at 1719.87,5655.4 h60
  text "TOP - BOTTOM" at 1967.07,5655.4 h60
  text "2" at 332.44,5531.44 h60
  text "157.48mil (4.000mm)" at 574.91,5531.44 h60
  text "-" at 1147.39,5531.44 h60
  text "PTH" at 1719.87,5531.44 h60
  text "TOP - BOTTOM" at 1967.07,5531.44 h60
  text "5" at 332.44,5407.49 h60
  text "160.00mil (4.064mm)" at 574.91,5407.49 h60
  text "-" at 1147.39,5407.49 h60
  text "NPTH" at 1719.87,5407.49 h60
  text "TOP - BOTTOM" at 1967.07,5407.49 h60
  text "Slot definitions :" at 50.87,5320.72 h60
  text "Routed Path Length" at 458.88,5320.72 h60
  text "= Calculated from tool start centre position to tool end centre position." at 964.53,5320.72 h60
  text "Hole Length" at 458.88,5271.13 h60
  text "= Routed Path Length + Tool Size = Slot length as defined in the PCB layout" at 776.86,5271.13 h60
  text "FOR 7.87MIL DRILL +0/-7.87MIL" at 220.6,5050 h60
  text "FOR 12.20 MIL DRILL +0/-12.20MIL" at 220.52,4945.19 h60
  text "FOR PTH +/-3MIL" at 224.82,4824.79 h60
  text "FOR NPTH +/-2MIL" at 224.82,4670 h60
  text "Symbol" at 3387.87,4243.23 h72
  text "Count" at 3669.44,4243.23 h72
  text "Hole Size" at 3911.91,4243.23 h72
  text "Hole Length" at 4428.44,4243.23 h72
  text "Plated" at 4840.37,4243.23 h72
  text "Drill Layer Pair" at 5087.57,4243.23 h72
  text "700" at 3669.44,4119.27 h60
  text "5.90mil (0.150mm)" at 3911.91,4119.27 h60
  text "-" at 4428.44,4119.27 h60
  text "PTH" at 4840.37,4119.27 h60
  text "TOP - L2-GND1" at 5087.57,4119.27 h60
  text "FOR 5.90 MIL DRILL +0/-5.90MIL" at 3460,3900 h60
  text "FAB_DWG" at -1322.95,-1032.44 h60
